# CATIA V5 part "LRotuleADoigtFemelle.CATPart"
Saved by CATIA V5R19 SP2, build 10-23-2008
Part number: RotuleADoigtFemelle
Publications: "Centre", "Plan", "Facteur d'échelle"
Bounding box of the stored display mesh (mm): x -4.763 to 4.763, y 0 to 5.5, z -4.755 to 4.755
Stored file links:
  E:\Mes documents\03_Ressources pédagogiques\01_Catia\Buggy Dassault\SchemaCinematiqueFinal\LRotuleADoigtFemelle.CATPart
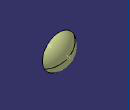
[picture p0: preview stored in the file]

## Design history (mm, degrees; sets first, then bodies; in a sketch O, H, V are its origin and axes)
External parameters (linked from other documents)
  `External.Facteur d'échelle` = 2
AxisSystem1: origin (0, 0, 0), X (1, 0, 0), Y (0, 1, 0), Z (0, 0, 1)
Body1 "RotuleADoigtFemelle" (main body)
  Circle1: type CtrRad, Start 90, End 150, Center vertex [YZ plane of AxisSystem1 | ZX plane of AxisSystem1 | XY plane of AxisSystem1], Support XY plane of AxisSystem1, Radius 5.5 {= 2.75mm*`External.Facteur d'échelle`}, FirstDirection (1, 0, 0)
  Revol1: Element1 Circle1, Line edge [YZ plane of AxisSystem1 | XY plane of AxisSystem1], Angle1 180
  Point1 "Centre": type Center, Curve Circle1
  Point2: (0, 0, 0), relative to vertex of Circle1, in AxisSystem1
  Circle2: type CtrRad, Start 90, End 150, Center Point1, Support xy-plane, Radius 5.5 {= 2.75mm*`External.Facteur d'échelle`}, FirstDirection (1, 0, 0)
